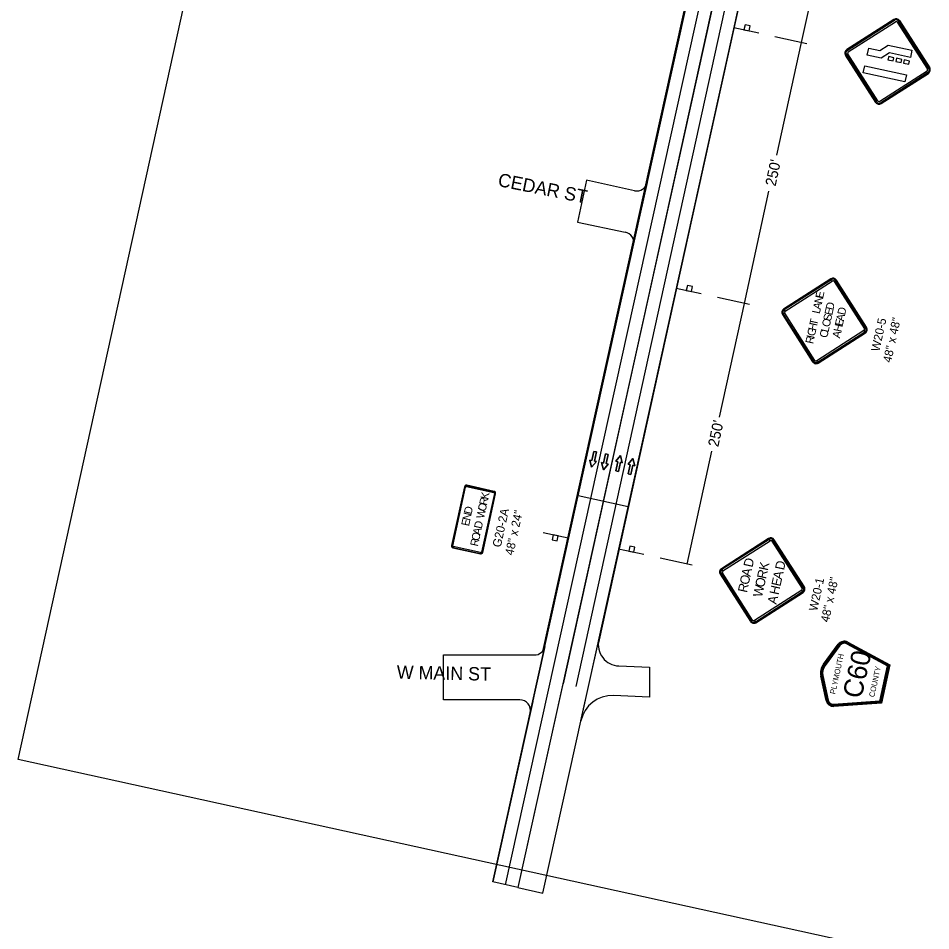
# Model space of a CAD drawing. Extents: x 14104283 to 14121738, y 8635219 to 8671666.
# Drawn here: x 14106925 to 14107780, y 8637146 to 8638001 of the extents above; entities that cross this region are included whole.
import ezdxf

# ---------------------------------------------------------------- set-up
doc = ezdxf.new("R2010")
doc.units = 0
for name, color, linetype in [('Cell', 7, 'Continuous'), ('Default', 7, 'Continuous'), ('dsnNonPlotable', 7, 'Continuous'), ('dsnPaintExistingBrokenLaneLineWhite', 7, 'Continuous'), ('dsnPaintExistingDoubleCenterYellow', 7, 'Continuous'), ('dsnPaintExistingEdgeLineRightWhite', 7, 'Continuous'), ('dsnStdLabel', 7, 'Continuous'), ('dsnTextOverlapOdd', 7, 'Continuous'), ('Sign', 7, 'Continuous')]:
    doc.layers.add(name, color=color, linetype=linetype)

msp = doc.modelspace()

# ---------------------------------------------------------------- linework, layer by layer
at = {"layer": 'Cell'}
for p, q in [((14107745.09, 8637999.71), (14107700.87, 8637971.42)), ((14107700.87, 8637971.42), (14107745.09, 8637999.71)), ((14107745.6, 8637998.92), (14107701.37, 8637970.63)), ((14107777.78, 8637953.84), (14107749.48, 8637998.07)), ((14107778.57, 8637954.35), (14107750.27, 8637998.57)), ((14107750.27, 8637998.57), (14107778.57, 8637954.35)), ((14107618.57, 8637986.78), (14107595.13, 8637991.93)), ((14107702.22, 8637969.31), (14107746.44, 8637997.61)), ((14107748.17, 8637997.23), (14107776.46, 8637953)), ((14107699.73, 8637966.24), (14107728.02, 8637922.01)), ((14107728.02, 8637922.01), (14107699.73, 8637966.24)), ((14107700.52, 8637966.74), (14107728.81, 8637922.52)), ((14107700.87, 8637971.42), (14107700.87, 8637971.42)), ((14107730.13, 8637923.36), (14107701.84, 8637967.59)), ((14107702.22, 8637969.31), (14107702.21, 8637969.31)), ((14107776.08, 8637951.28), (14107731.86, 8637922.98)), ((14107732.7, 8637921.67), (14107776.92, 8637949.96)), ((14107733.2, 8637920.88), (14107777.43, 8637949.17)), ((14107777.43, 8637949.17), (14107733.2, 8637920.88)), ((14107686.03, 8637756.73), (14107641.8, 8637728.43)), ((14107686.53, 8637755.94), (14107687.37, 8637754.62)), ((14107689.1, 8637754.24), (14107690.42, 8637755.08)), ((14107719.5, 8637711.36), (14107691.21, 8637755.59)), ((14107564.62, 8637742.67), (14107541.18, 8637747.82)), ((14107641.45, 8637723.76), (14107642.77, 8637724.6)), ((14107643.15, 8637726.33), (14107642.31, 8637727.64)), ((14107640.66, 8637723.25), (14107668.96, 8637679.03)), ((14107717.01, 8637708.29), (14107717.86, 8637706.97)), ((14107718.71, 8637710.86), (14107717.39, 8637710.02)), ((14107674.14, 8637677.89), (14107718.36, 8637706.18)), ((14107671.06, 8637680.38), (14107669.75, 8637679.53)), ((14107673.63, 8637678.68), (14107672.79, 8637680)), ((14107342.77, 8637561.94), (14107330.7, 8637507)), ((14107344.74, 8637562.15), (14107344.9, 8637562.92)), ((14107370.64, 8637557.74), (14107345, 8637563.37)), ((14107343.23, 8637561.84), (14107343.99, 8637561.68)), ((14107360, 8637500.57), (14107372.07, 8637555.51)), ((14107370.54, 8637557.28), (14107370.37, 8637556.52)), ((14107370.85, 8637555.78), (14107371.61, 8637555.61)), ((14107416.71, 8637519.21), (14107440.15, 8637514.06)), ((14107627.73, 8637513.57), (14107583.51, 8637485.28)), ((14107628.24, 8637512.78), (14107629.08, 8637511.46)), ((14107630.81, 8637511.09), (14107632.12, 8637511.93)), ((14107661.21, 8637468.21), (14107632.91, 8637512.43)), ((14107331.92, 8637506.74), (14107331.16, 8637506.9)), ((14107332.13, 8637504.77), (14107357.77, 8637499.14)), ((14107332.23, 8637505.23), (14107332.4, 8637505.99)), ((14107510.73, 8637498.55), (14107487.29, 8637503.7)), ((14107358.04, 8637500.36), (14107357.87, 8637499.6)), ((14107359.54, 8637500.67), (14107358.78, 8637500.84)), ((14107582.37, 8637480.1), (14107610.67, 8637435.87)), ((14107583.16, 8637480.6), (14107584.48, 8637481.44)), ((14107584.86, 8637483.17), (14107584.02, 8637484.49)), ((14107615.85, 8637434.73), (14107660.07, 8637463.03)), ((14107658.72, 8637465.13), (14107659.56, 8637463.82)), ((14107660.42, 8637467.7), (14107659.1, 8637466.86)), ((14107612.77, 8637437.22), (14107611.46, 8637436.38)), ((14107615.34, 8637435.53), (14107614.5, 8637436.84))]:
    msp.add_line(p, q, dxfattribs=at)
for points in [[(14107701.37, 8637970.63), (14107745.6, 8637998.92)], [(14107749.48, 8637998.07), (14107777.78, 8637953.84)], [(14107604.57, 8637989.94), (14107609.37, 8637988.89), (14107610.42, 8637993.68), (14107605.62, 8637994.74), (14107604.57, 8637989.94)], [(14107702.21, 8637969.31), (14107746.44, 8637997.61)], [(14107748.17, 8637997.23), (14107776.46, 8637953)], [(14107728.81, 8637922.52), (14107700.52, 8637966.74)], [(14107730.13, 8637923.36), (14107701.84, 8637967.59)], [(14107776.08, 8637951.28), (14107731.86, 8637922.98)], [(14107776.92, 8637949.96), (14107732.7, 8637921.67)], [(14107550.62, 8637745.83), (14107555.41, 8637744.78), (14107556.46, 8637749.57), (14107551.67, 8637750.63), (14107550.62, 8637745.83)], [(14107462.11, 8637586.65), (14107460.28, 8637587.05), (14107462, 8637580.28), (14107466.38, 8637585.72), (14107464.55, 8637586.12), (14107466.42, 8637594.67), (14107463.97, 8637595.2), (14107462.11, 8637586.65)], [(14107473.17, 8637584.22), (14107471.34, 8637584.62), (14107473.06, 8637577.85), (14107477.44, 8637583.29), (14107475.61, 8637583.69), (14107477.48, 8637592.24), (14107475.04, 8637592.77), (14107473.17, 8637584.22)], [(14107488.87, 8637584.97), (14107490.7, 8637584.57), (14107488.98, 8637591.35), (14107484.6, 8637585.91), (14107486.43, 8637585.51), (14107484.56, 8637576.96), (14107487.01, 8637576.43), (14107488.87, 8637584.97)], [(14107500.51, 8637582.16), (14107502.34, 8637581.76), (14107500.62, 8637588.53), (14107496.23, 8637583.09), (14107498.06, 8637582.69), (14107496.2, 8637574.14), (14107498.64, 8637573.61), (14107500.51, 8637582.16)], [(14107430.72, 8637516.05), (14107425.92, 8637517.1), (14107424.87, 8637512.3), (14107429.66, 8637511.25), (14107430.72, 8637516.05)], [(14107496.73, 8637501.71), (14107501.52, 8637500.66), (14107502.58, 8637505.45), (14107497.78, 8637506.51), (14107496.73, 8637501.71)]]:
    msp.add_lwpolyline(points, dxfattribs=at)
for points in [[(14107604.57, 8637989.94), (14107609.37, 8637988.89), (14107610.42, 8637993.68), (14107605.62, 8637994.74)], [(14107731.77, 8637970.62), (14107739.66, 8637975.67), (14107761.93, 8637970.78), (14107760.48, 8637964.18), (14107740.95, 8637968.48), (14107733.05, 8637963.43), (14107719.99, 8637966.29), (14107721.44, 8637972.89)], [(14107740.17, 8637964.93), (14107739.52, 8637962), (14107744.41, 8637960.93), (14107745.05, 8637963.86)], [(14107717.82, 8637956.4), (14107756.89, 8637947.82), (14107755.44, 8637941.23), (14107716.37, 8637949.81)], [(14107747.49, 8637963.32), (14107746.85, 8637960.39), (14107751.73, 8637959.32), (14107752.38, 8637962.25)], [(14107754.82, 8637961.72), (14107754.17, 8637958.78), (14107759.06, 8637957.71), (14107759.7, 8637960.64)], [(14107550.62, 8637745.83), (14107555.41, 8637744.78), (14107556.46, 8637749.57), (14107551.67, 8637750.63)], [(14107686.53, 8637755.94), (14107642.31, 8637727.64), (14107643.15, 8637726.33), (14107687.37, 8637754.62), (14107686.53, 8637755.94)], [(14107718.71, 8637710.86), (14107690.42, 8637755.08), (14107689.1, 8637754.24), (14107717.39, 8637710.02), (14107718.71, 8637710.86)], [(14107641.45, 8637723.76), (14107669.75, 8637679.53), (14107671.06, 8637680.38), (14107642.77, 8637724.6), (14107641.45, 8637723.76)], [(14107673.63, 8637678.68), (14107717.86, 8637706.97), (14107717.01, 8637708.29), (14107672.79, 8637680), (14107673.63, 8637678.68)], [(14107463.97, 8637595.2), (14107466.42, 8637594.67), (14107464.55, 8637586.12), (14107466.38, 8637585.72), (14107462, 8637580.28), (14107460.28, 8637587.05), (14107462.11, 8637586.65)], [(14107475.04, 8637592.77), (14107477.48, 8637592.24), (14107475.61, 8637583.69), (14107477.44, 8637583.29), (14107473.06, 8637577.85), (14107471.34, 8637584.62), (14107473.17, 8637584.22)], [(14107487.01, 8637576.43), (14107484.56, 8637576.96), (14107486.43, 8637585.51), (14107484.6, 8637585.91), (14107488.98, 8637591.35), (14107490.7, 8637584.57), (14107488.87, 8637584.97)], [(14107498.64, 8637573.61), (14107496.2, 8637574.14), (14107498.06, 8637582.69), (14107496.23, 8637583.09), (14107500.62, 8637588.53), (14107502.34, 8637581.76), (14107500.51, 8637582.16)], [(14107370.54, 8637557.28), (14107344.9, 8637562.92), (14107344.74, 8637562.15), (14107370.37, 8637556.52), (14107370.54, 8637557.28)], [(14107343.23, 8637561.84), (14107331.16, 8637506.9), (14107331.92, 8637506.74), (14107343.99, 8637561.68), (14107343.23, 8637561.84)], [(14107359.54, 8637500.67), (14107371.61, 8637555.61), (14107370.85, 8637555.78), (14107358.78, 8637500.84), (14107359.54, 8637500.67)], [(14107430.72, 8637516.05), (14107425.92, 8637517.1), (14107424.87, 8637512.3), (14107429.66, 8637511.25)], [(14107628.24, 8637512.78), (14107584.02, 8637484.49), (14107584.86, 8637483.17), (14107629.08, 8637511.46), (14107628.24, 8637512.78)], [(14107660.42, 8637467.7), (14107632.12, 8637511.93), (14107630.81, 8637511.09), (14107659.1, 8637466.86), (14107660.42, 8637467.7)], [(14107332.23, 8637505.23), (14107357.87, 8637499.6), (14107358.04, 8637500.36), (14107332.4, 8637505.99), (14107332.23, 8637505.23)], [(14107496.73, 8637501.71), (14107501.52, 8637500.66), (14107502.58, 8637505.45), (14107497.78, 8637506.51)], [(14107583.16, 8637480.6), (14107611.46, 8637436.38), (14107612.77, 8637437.22), (14107584.48, 8637481.44), (14107583.16, 8637480.6)], [(14107615.34, 8637435.53), (14107659.56, 8637463.82), (14107658.72, 8637465.13), (14107614.5, 8637436.84), (14107615.34, 8637435.53)]]:
    msp.add_lwpolyline(points, close=True, dxfattribs=at)
for centre, radius, start, end in [((14107747.11, 8637996.55), 3.75, 32.61038, 122.61001), ((14107747.11, 8637996.55), 3.75, 32.61038, 122.61001), ((14107747.11, 8637996.55), 2.81, 32.61038, 122.61001), ((14107747.11, 8637996.55), 2.81, 32.61038, 122.61001), ((14107747.11, 8637996.55), 1.25, 32.61038, 122.61001), ((14107747.11, 8637996.55), 1.25, 32.61038, 122.61001), ((14107702.89, 8637968.26), 3.75, 122.6102, 212.60995), ((14107702.89, 8637968.26), 3.75, 122.6102, 212.60995), ((14107702.89, 8637968.26), 2.81, 122.6102, 212.60995), ((14107702.89, 8637968.26), 2.81, 122.6102, 212.60995), ((14107702.89, 8637968.26), 1.25, 122.6102, 212.60995), ((14107702.89, 8637968.26), 1.25, 122.6102, 212.60995), ((14107775.41, 8637952.33), 1.25, 302.61016, 32.61038), ((14107775.41, 8637952.33), 1.25, 302.61016, 32.61038), ((14107775.41, 8637952.33), 2.81, 302.61016, 32.61038), ((14107775.41, 8637952.33), 2.81, 302.61016, 32.61038), ((14107775.41, 8637952.33), 3.75, 302.61016, 32.61038), ((14107775.41, 8637952.33), 3.75, 302.61016, 32.61038), ((14107731.18, 8637924.03), 3.75, 212.60995, 302.61016), ((14107731.18, 8637924.03), 3.75, 212.60995, 302.61016), ((14107731.18, 8637924.03), 2.81, 212.60995, 302.61016), ((14107731.18, 8637924.03), 2.81, 212.60995, 302.61016), ((14107731.18, 8637924.03), 1.25, 212.60995, 302.61016), ((14107731.18, 8637924.03), 1.25, 212.60995, 302.61016), ((14107688.05, 8637753.57), 3.75, 32.61038, 122.61001), ((14107688.05, 8637753.57), 2.81, 32.61038, 122.61001), ((14107688.05, 8637753.57), 1.25, 32.61038, 122.61001), ((14107643.82, 8637725.27), 3.75, 122.6102, 212.60995), ((14107643.82, 8637725.27), 2.81, 122.6102, 212.60995), ((14107643.82, 8637725.27), 1.25, 122.6102, 212.60995), ((14107716.34, 8637709.34), 1.25, 302.61016, 32.61038), ((14107716.34, 8637709.34), 2.81, 302.61016, 32.61038), ((14107716.34, 8637709.34), 3.75, 302.61016, 32.61038), ((14107672.12, 8637681.05), 3.75, 212.60995, 302.61016), ((14107672.12, 8637681.05), 2.81, 212.60995, 302.61016), ((14107672.12, 8637681.05), 1.25, 212.60995, 302.61016), ((14107344.6, 8637561.54), 1.87, 77.61021, 167.61042), ((14107344.6, 8637561.54), 1.41, 77.61021, 167.61042), ((14107344.6, 8637561.54), 0.625, 77.61021, 167.61042), ((14107370.24, 8637555.91), 0.625, 347.61027, 77.61048), ((14107370.24, 8637555.91), 1.41, 347.61027, 77.61048), ((14107370.24, 8637555.91), 1.87, 347.61027, 77.61048), ((14107629.75, 8637510.41), 3.75, 32.61038, 122.61001), ((14107629.75, 8637510.41), 2.81, 32.61038, 122.61001), ((14107629.75, 8637510.41), 1.25, 32.61038, 122.61001), ((14107332.53, 8637506.6), 1.87, 167.61042, 257.61006), ((14107332.53, 8637506.6), 1.41, 167.61042, 257.61006), ((14107332.53, 8637506.6), 0.625, 167.61042, 257.61006), ((14107358.17, 8637500.97), 1.87, 257.61006, 347.61027), ((14107358.17, 8637500.97), 1.41, 257.61006, 347.61027), ((14107358.17, 8637500.97), 0.625, 257.61006, 347.61027), ((14107585.53, 8637482.12), 3.75, 122.6102, 212.60995), ((14107585.53, 8637482.12), 2.81, 122.6102, 212.60995), ((14107585.53, 8637482.12), 1.25, 122.6102, 212.60995), ((14107658.05, 8637466.19), 3.75, 302.61016, 32.61038), ((14107658.05, 8637466.19), 1.25, 302.61016, 32.61038), ((14107658.05, 8637466.19), 2.81, 302.61016, 32.61038), ((14107613.82, 8637437.89), 3.75, 212.60995, 302.61016), ((14107613.82, 8637437.89), 2.81, 212.60995, 302.61016), ((14107613.82, 8637437.89), 1.25, 212.60995, 302.61016)]:
    msp.add_arc(centre, radius, start, end, dxfattribs=at)
at = {"layer": 'Default'}
for p, q in [((14107457.32, 8637849.19), (14107448.62, 8637809.68)), ((14107502.22, 8637839.3), (14107457.32, 8637849.19)), ((14107501.26, 8637788.6), (14107514.14, 8637846.91)), ((14107448.62, 8637809.68), (14107493.49, 8637800.56)), ((14107451.98, 8637342.9), (14107468.68, 8637418.51)), ((14107418.16, 8637412.31), (14107404.47, 8637350.31)), ((14107323.16, 8637404.47), (14107408.39, 8637404.47)), ((14107323.16, 8637362.47), (14107323.16, 8637404.47)), ((14107487.45, 8637394.21), (14107516.02, 8637393.12)), ((14107516.02, 8637393.12), (14107516.02, 8637365.12)), ((14107516.02, 8637365.12), (14107482.42, 8637366.4)), ((14107394.7, 8637362.47), (14107323.16, 8637362.47))]:
    msp.add_line(p, q, dxfattribs=at)
for points in [[(14107392.92, 8637186.73), (14107369.48, 8637191.91), (14107655.09, 8638485.14), (14107678.52, 8638479.96)], [(14107602.34, 8638246.31), (14107649.23, 8638236.01), (14107496.22, 8637543.21), (14107449.34, 8637553.51)], [(14107416.35, 8637181.55), (14107649.12, 8638235.55), (14107625.69, 8638240.73), (14107392.92, 8637186.73)]]:
    msp.add_lwpolyline(points, close=True, dxfattribs=at)
for centre, radius, start, end in [((14107504.37, 8637849.06), 10, 257.58106, 347.54626), ((14107491.49, 8637790.76), 10, 347.54626, 78.50271), ((14107488.21, 8637414.2), 20, 167.54626, 267.81775), ((14107408.39, 8637414.47), 10, 270, 347.54626), ((14107481.28, 8637336.43), 30, 87.81775, 167.54626), ((14107394.7, 8637352.47), 10, 347.54626, 90)]:
    msp.add_arc(centre, radius, start, end, dxfattribs=at)
at = {"layer": 'dsnNonPlotable'}
msp.add_lwpolyline([(14106924.98, 8637306.69), (14107261.36, 8638837.67), (14108247.83, 8638620.92), (14107911.44, 8637089.94)], close=True, dxfattribs=at)
at = {"layer": 'dsnPaintExistingBrokenLaneLineWhite'}
for p, q in [((14107381.2, 8637189.32), (14107721.79, 8638731.54)), ((14107447.5, 8637375.04), (14107637.12, 8638238.2))]:
    msp.add_line(p, q, dxfattribs=at)
at = {"layer": 'dsnPaintExistingDoubleCenterYellow'}
msp.add_line((14107435.78, 8637377.61), (14107677.97, 8638480.08), dxfattribs=at)
at = {"layer": 'dsnPaintExistingEdgeLineRightWhite'}
for p, q in [((14107468.79, 8637415.99), (14107828.52, 8639053.57)), ((14107708.89, 8638734.37), (14107415.88, 8637407.61)), ((14107406.84, 8637361.06), (14107369.48, 8637191.91))]:
    msp.add_line(p, q, dxfattribs=at)
at = {"layer": 'dsnStdLabel'}
for p, q in [((14107658.66, 8637977.98), (14107681.84, 8638083.5)), ((14107663.54, 8637976.9), (14107633.43, 8637983.52)), ((14107635.5, 8637872.53), (14107658.66, 8637977.98)), ((14107605.02, 8637733.8), (14107628.07, 8637838.73)), ((14107609.9, 8637732.72), (14107579.79, 8637739.34)), ((14107581.6, 8637627.19), (14107605.02, 8637733.8)), ((14107551.38, 8637489.62), (14107574.63, 8637595.47)), ((14107556.26, 8637488.55), (14107526.15, 8637495.16))]:
    msp.add_line(p, q, dxfattribs=at)
at = {"layer": 'Sign'}
for p, q in [((14107679.05, 8637395.78), (14107692.99, 8637414.59)), ((14107693.77, 8637414.01), (14107679.84, 8637395.2)), ((14107679.84, 8637395.2), (14107693.77, 8637414.01)), ((14107680.62, 8637394.62), (14107694.55, 8637413.43)), ((14107694.55, 8637413.43), (14107680.62, 8637394.62)), ((14107700.98, 8637414.86), (14107739.15, 8637394.21)), ((14107739.15, 8637394.21), (14107700.98, 8637414.86)), ((14107740.26, 8637394.71), (14107701.44, 8637415.71)), ((14107701.44, 8637415.71), (14107740.26, 8637394.71)), ((14107701.9, 8637416.57), (14107741.36, 8637395.22)), ((14107739.15, 8637394.21), (14107731.93, 8637361.14)), ((14107731.93, 8637361.14), (14107739.15, 8637394.21)), ((14107732.73, 8637360.21), (14107740.26, 8637394.71)), ((14107740.26, 8637394.71), (14107732.73, 8637360.21)), ((14107741.36, 8637395.22), (14107733.52, 8637359.29)), ((14107741.36, 8637395.22), (14107740.26, 8637394.71)), ((14107681.48, 8637361.84), (14107676.64, 8637384.74)), ((14107677.6, 8637384.94), (14107682.43, 8637362.04)), ((14107682.43, 8637362.04), (14107677.6, 8637384.94)), ((14107683.38, 8637362.24), (14107678.55, 8637385.14)), ((14107678.55, 8637385.14), (14107683.38, 8637362.24)), ((14107731.93, 8637361.14), (14107688.63, 8637358.26)), ((14107688.63, 8637358.26), (14107731.93, 8637361.14)), ((14107688.69, 8637357.29), (14107732.73, 8637360.21)), ((14107732.73, 8637360.21), (14107688.69, 8637357.29)), ((14107733.52, 8637359.29), (14107688.76, 8637356.32)), ((14107731.93, 8637361.14), (14107732.73, 8637360.21))]:
    msp.add_line(p, q, dxfattribs=at)
for centre, radius, start, end in [((14107698.59, 8637410.44), 6.97, 61.58827, 143.46107), ((14107698.59, 8637410.44), 5.99, 61.58827, 143.46107), ((14107698.59, 8637410.44), 5.99, 61.58827, 143.46107), ((14107698.59, 8637410.44), 5.02, 61.58827, 143.46107), ((14107698.59, 8637410.44), 5.02, 61.58827, 143.46107), ((14107690.12, 8637387.58), 13.77, 143.46107, 191.92127), ((14107690.12, 8637387.58), 12.8, 143.46107, 191.92127), ((14107690.12, 8637387.58), 12.8, 143.46107, 191.92127), ((14107690.12, 8637387.58), 11.83, 143.46107, 191.92127), ((14107690.12, 8637387.58), 11.83, 143.46107, 191.92127), ((14107688.3, 8637363.27), 6.97, 191.92127, 273.79407), ((14107688.3, 8637363.27), 5.99, 191.92127, 273.79407), ((14107688.3, 8637363.27), 5.99, 191.92127, 273.79407), ((14107688.3, 8637363.27), 5.02, 191.92127, 273.79407), ((14107688.3, 8637363.27), 5.02, 191.92127, 273.79407)]:
    msp.add_arc(centre, radius, start, end, dxfattribs=at)

# ---------------------------------------------------------------- texts
at = {"layer": 'Cell'}
for s, height, p in [('E', 7.5, (14107678.72, 8637738.07)), ('A', 7.5, (14107676.4, 8637727.52)), ('N', 7.5, (14107677.6, 8637732.97)), ('D', 7.5, (14107688.3, 8637727.06)), ('L', 7.5, (14107675.54, 8637723.56)), ('E', 7.5, (14107687.23, 8637722.16)), ('D', 7.5, (14107699.26, 8637722.33)), ('T', 7.5, (14107673.12, 8637712.57)), ('O', 7.5, (14107684.81, 8637711.14)), ('S', 7.5, (14107686.01, 8637716.61)), ('E', 7.5, (14107697, 8637712.04)), ('A', 7.5, (14107697.99, 8637716.53)), ('W20-5', 8, (14107731.41, 8637688.21)), ('48" x 48"', 8, (14107742.43, 8637677.79)), ('G', 7.5, (14107670.93, 8637702.59)), ('H', 7.5, (14107672.05, 8637707.69)), ('C', 7.5, (14107682.58, 8637701)), ('L', 7.5, (14107683.73, 8637706.24)), ('A', 7.5, (14107694.51, 8637700.7)), ('H', 7.5, (14107695.79, 8637706.51)), ('R', 7.5, (14107669.34, 8637695.36)), ('I', 7.5, (14107670.46, 8637700.46)), ('K', 7.5, (14107365.03, 8637549.66)), ('O', 7.5, (14107362.55, 8637538.4)), ('R', 7.5, (14107363.82, 8637544.15)), ('N', 7.5, (14107348.2, 8637529.88)), ('D', 7.5, (14107349.5, 8637535.78)), ('W', 7.5, (14107361.08, 8637531.69)), ('G20-2A', 8, (14107376.79, 8637504.77)), ('48" x 24"', 8, (14107388.46, 8637497.29)), ('E', 7.5, (14107347.06, 8637524.69)), ('D', 7.5, (14107358.99, 8637522.19)), ('A', 7.5, (14107357.72, 8637516.4)), ('R', 7.5, (14107355.38, 8637505.74)), ('O', 7.5, (14107356.52, 8637510.95)), ('D', 8.75, (14107612.56, 8637486.05)), ('K', 8.75, (14107626.92, 8637482.96)), ('D', 8.75, (14107642.08, 8637483.5)), ('O', 8.75, (14107608.98, 8637469.72)), ('A', 8.75, (14107610.65, 8637477.32)), ('O', 8.75, (14107623.46, 8637467.21)), ('R', 8.75, (14107625.22, 8637475.22)), ('E', 8.75, (14107638.73, 8637468.24)), ('A', 8.75, (14107640.13, 8637474.61)), ('48" x 48"', 8, (14107684.13, 8637434.63)), ('R', 8.75, (14107607.37, 8637462.39)), ('W', 8.75, (14107621.47, 8637458.12)), ('H', 8.75, (14107636.99, 8637460.31)), ('W20-1', 8, (14107673.12, 8637445.09)), ('A', 8.75, (14107635.03, 8637451.42))]:
    msp.add_text(s, height=height, rotation=77.61021, dxfattribs=at).set_placement(p)
at = {"layer": 'dsnStdLabel'}
for p in [(14107634.21, 8637842.93), (14107580.57, 8637598.76)]:
    msp.add_text("250'", height=10, rotation=78.05307, dxfattribs=at).set_placement(p)
at = {"layer": 'dsnTextOverlapOdd'}
for s, rotation, p in [('CEDAR ST', 348.69117, (14107373.5, 8637843.78)), ('W MAIN ST', 358.69117, (14107279.34, 8637382.3))]:
    msp.add_text(s, height=12.5, rotation=rotation, dxfattribs=at).set_placement(p)
at = {"layer": 'Sign'}
for s, height, p in [('C60', 18.144, (14107714.57, 8637362.83)), ('PLYMOUTH', 5.184, (14107690.12, 8637367.4)), ('COUNTY', 5.184, (14107726.7, 8637364.63))]:
    msp.add_text(s, height=height, rotation=77.69117, dxfattribs=at).set_placement(p)

doc.saveas('drawing.dxf')
